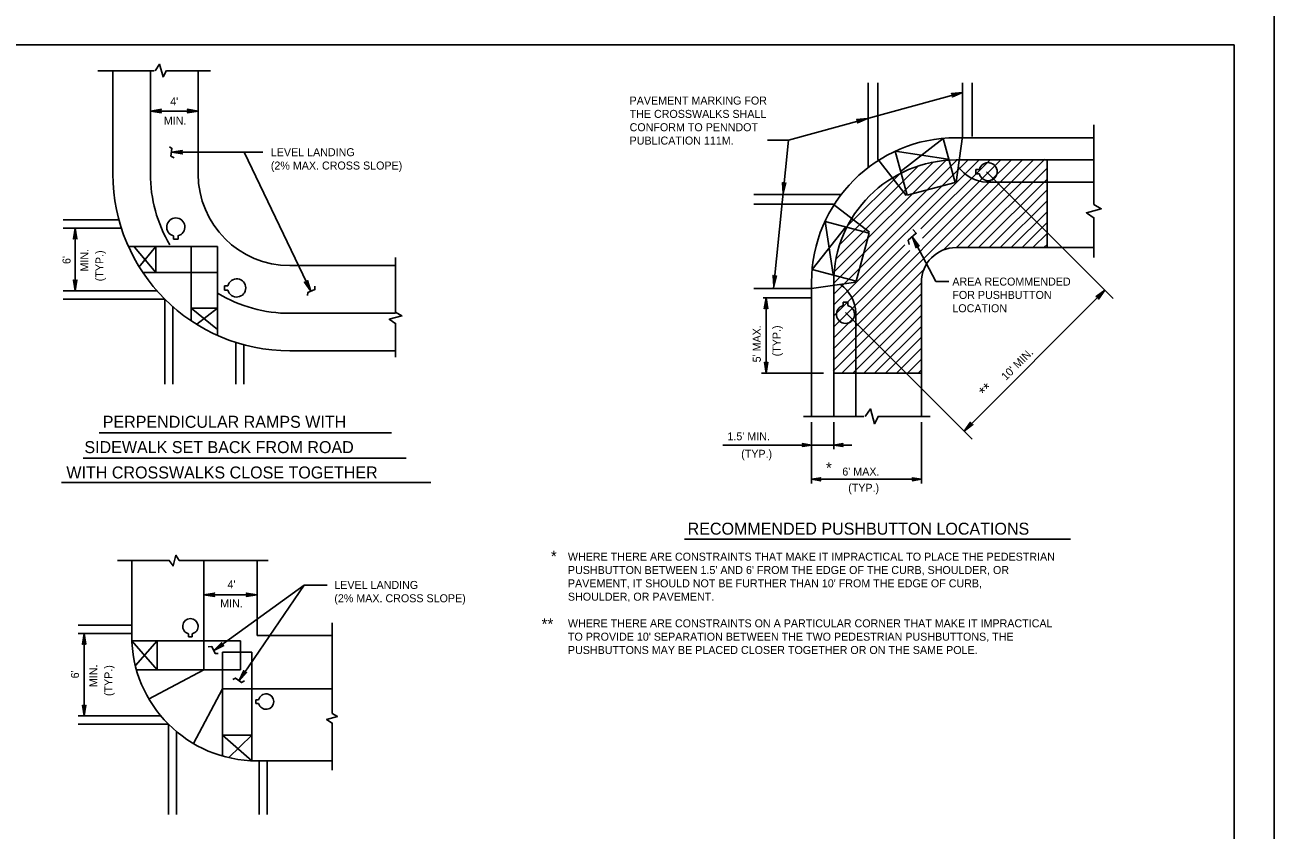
# Model space of a CAD drawing. Extents: x 36 to 940, y -1166 to 1210.
# Drawn here: x 408.6 to 876.9, y -881.2 to -579.3 of the extents above; entities that cross this region are included whole.
import ezdxf

# ---------------------------------------------------------------- set-up
doc = ezdxf.new("R2010")
doc.units = 0
for name, color, linetype in [('1', 7, 'Continuous'), ('2', 7, 'Continuous'), ('PLT-BNDY', 7, 'Continuous')]:
    doc.layers.add(name, color=color, linetype=linetype)

msp = doc.modelspace()

# ---------------------------------------------------------------- linework, layer by layer
at = {"layer": '1'}
for p in [(75.86, -586.83), (861.86, -1150.83)]:
    msp.add_line(p, (861.86, -586.83), dxfattribs=at)
at = {"layer": '2'}
for p, q in [((457, -596.52), (435.99, -596.52)), ((441.58, -596.52), (441.58, -635.21)), ((455.74, -635.21), (455.74, -596.52)), ((478.16, -596.52), (461.63, -596.52)), ((473.55, -596.52), (473.55, -635.21)), ((724.73, -632.8), (724.73, -601)), ((728.34, -629.69), (728.34, -601)), ((760.03, -621.2), (760.03, -601)), ((763.64, -621.2), (763.64, -601)), ((694.86, -622.48), (760.03, -604.62)), ((473.55, -611.6), (455.74, -611.6)), ((809.33, -646.61), (809.33, -616.73)), ((694.86, -622.48), (687.02, -622.48)), ((694.86, -622.48), (689.22, -678.1)), ((752.88, -621.85), (736.76, -634.41)), ((757.31, -638.38), (752.88, -621.85)), ((757.68, -638.28), (760.03, -621.2)), ((809.33, -621.63), (757.68, -621.63)), ((463.58, -627.06), (497.74, -627.06)), ((490.74, -627.06), (515.74, -679.16)), ((739.29, -643.21), (734.86, -626.67)), ((734.86, -626.67), (754.56, -629.71)), ((711.63, -700.88), (782.74, -629.77)), ((711.66, -696.76), (778.63, -629.8)), ((711.76, -684.4), (766.27, -629.89)), ((711.79, -680.29), (762.15, -629.92)), ((711.82, -676.17), (758.03, -629.96)), ((712.03, -671.87), (753.78, -630.12)), ((712.6, -667.21), (749.03, -630.78)), ((714.05, -661.68), (743.67, -632.05)), ((738.92, -643.31), (728.34, -629.69)), ((744.42, -655.83), (770.39, -629.86)), ((745.03, -659.3), (774.51, -629.83)), ((752.85, -663.74), (786.86, -629.73)), ((809.33, -629.96), (757.68, -629.96)), ((757.87, -662.81), (790.98, -629.7)), ((791.76, -662.81), (791.76, -629.7)), ((716.59, -655.05), (736.66, -634.97)), ((761.96, -662.81), (791.76, -633.01)), ((765.12, -633.52), (765.12, -635.17)), ((766.42, -633.52), (765.12, -633.52)), ((765.12, -635.17), (766.42, -635.17)), ((816.56, -681.88), (769.02, -634.35)), ((739.29, -643.21), (757.31, -638.38)), ((766.05, -662.81), (791.76, -637.1)), ((809.33, -638.28), (769.2, -638.28)), ((770.13, -662.81), (791.76, -641.18)), ((714.67, -642.87), (681.91, -642.87)), ((774.22, -662.81), (791.76, -645.27)), ((711.55, -646.48), (681.91, -646.48)), ((725.18, -657.05), (711.55, -646.48)), ((778.31, -662.81), (791.76, -649.36)), ((443.85, -652.43), (422.94, -652.43)), ((444.76, -655.5), (422.94, -655.5)), ((427.45, -679.04), (427.45, -655.5)), ((703.71, -671.01), (716.3, -655.08)), ((725.08, -657.43), (708.54, -652.99)), ((708.54, -652.99), (711.6, -672.88)), ((782.4, -662.81), (791.76, -653.44)), ((809.33, -666.51), (809.33, -651.6)), ((464.33, -658.41), (464.33, -659.71)), ((464.33, -659.71), (465.99, -659.71)), ((465.99, -659.71), (465.99, -658.41)), ((720.25, -675.45), (725.08, -657.43)), ((741.37, -658.97), (750.03, -675.48)), ((786.48, -662.81), (791.76, -657.53)), ((480.74, -662.38), (447.4, -662.38)), ((457.63, -672.17), (449.7, -662.65)), ((457.63, -662.38), (451.34, -670.22)), ((457.63, -662.38), (457.63, -672.17)), ((470.95, -662.38), (470.95, -690.29)), ((480.74, -662.38), (480.74, -695.72)), ((711.69, -692.64), (740.38, -663.96)), ((711.73, -688.52), (738.44, -661.81)), ((809.33, -662.81), (757.68, -662.81)), ((790.57, -662.81), (791.76, -661.62)), ((547.58, -687), (547.58, -666.58)), ((480.74, -672.17), (452.83, -672.17)), ((547.58, -669.57), (507.91, -669.57)), ((720.25, -675.45), (703.71, -671.01)), ((711.6, -705), (745.49, -671.1)), ((483.41, -678.78), (483.41, -677.13)), ((483.41, -677.13), (484.71, -677.13)), ((484.71, -678.78), (483.41, -678.78)), ((703.5, -678.1), (681.91, -678.1)), ((720.15, -675.82), (703.5, -678.1)), ((703.5, -726.17), (703.5, -675.82)), ((711.57, -709.12), (744.68, -676.01)), ((711.82, -726.17), (711.82, -675.82)), ((744.68, -726.17), (744.68, -675.82)), ((755.01, -675.48), (750.03, -675.48)), ((760.67, -731.62), (813.49, -678.81)), ((458.12, -679.04), (422.94, -679.04)), ((461.01, -682.11), (422.94, -682.11)), ((461.01, -682.11), (461.01, -714.01)), ((703.5, -681.72), (685.41, -681.72)), ((686.44, -709.9), (686.44, -681.72)), ((714.87, -709.9), (744.68, -680.1)), ((715.38, -683.26), (717.04, -683.26)), ((715.38, -684.56), (715.38, -683.26)), ((717.04, -683.26), (717.04, -684.56)), ((464.08, -684.99), (464.08, -714.01)), ((480.74, -685.48), (470.95, -685.48)), ((470.95, -685.48), (480.8, -693.54)), ((480.74, -685.48), (473.03, -691.5)), ((547.58, -687.47), (507.91, -687.47)), ((763.75, -734.69), (716.21, -687.16)), ((718.96, -709.9), (744.68, -684.18)), ((720.15, -726.17), (720.15, -687.33)), ((723.05, -709.9), (744.68, -688.27)), ((547.58, -703.91), (547.58, -691.24)), ((727.14, -709.9), (744.68, -692.36)), ((731.22, -709.9), (744.68, -696.44)), ((487.61, -698.36), (487.61, -714.01)), ((490.68, -699.26), (490.68, -714.01)), ((547.58, -701.54), (507.91, -701.54)), ((735.31, -709.9), (744.68, -700.53)), ((739.4, -709.9), (744.68, -704.62)), ((708.02, -709.9), (684.68, -709.9)), ((744.68, -709.9), (711.56, -709.9)), ((743.48, -709.9), (744.68, -708.71)), ((723.06, -726.17), (700.5, -726.17)), ((703.5, -751.29), (703.5, -728.34)), ((711.82, -738.46), (711.82, -728.34)), ((747.95, -726.17), (728.5, -726.17)), ((744.68, -751.29), (744.68, -728.34)), ((545.97, -732.32), (436.4, -732.32)), ((703.5, -736.86), (670.18, -736.86)), ((711.82, -736.86), (703.5, -736.86)), ((718.58, -736.86), (711.82, -736.86)), ((551.49, -741.73), (430.47, -741.73)), ((560.81, -750.94), (422.33, -750.94)), ((744.68, -749.7), (703.5, -749.7)), ((800.5, -772.21), (655.84, -772.21)), ((443.3, -780.18), (462.83, -780.18)), ((448.63, -780.18), (448.63, -808.32)), ((466.44, -780.18), (499.73, -780.18)), ((475.63, -780.18), (475.63, -821.23)), ((495.63, -780.18), (495.63, -808.31)), ((513.27, -789.38), (479.44, -813.91)), ((513.27, -789.38), (488.9, -825.19)), ((521.87, -789.38), (513.27, -789.38)), ((495.63, -793.01), (475.63, -793.01)), ((448.63, -804.47), (428.55, -804.47)), ((523.75, -837.5), (523.75, -803.53)), ((448.63, -807.54), (428.55, -807.54)), ((430.79, -838.47), (430.79, -807.54)), ((469.92, -807.65), (469.92, -808.75)), ((469.92, -808.75), (471.33, -808.75)), ((471.33, -808.75), (471.33, -807.65)), ((523.75, -808.31), (495.63, -808.31)), ((489.36, -810.31), (448.63, -810.31)), ((458.24, -821.23), (448.63, -810.31)), ((458.24, -810.31), (450.11, -819.58)), ((458.24, -810.31), (458.24, -821.23)), ((482.71, -814.58), (482.71, -853.5)), ((493.63, -814.58), (482.71, -814.58)), ((489.36, -810.31), (489.36, -821.23)), ((493.63, -814.58), (493.63, -855.3)), ((489.36, -821.23), (450.44, -821.23)), ((475.63, -821.23), (454.89, -832.21)), ((482.71, -828.31), (471.84, -848.84)), ((523.75, -828.31), (482.71, -828.31)), ((495.11, -833.78), (495.11, -832.37)), ((495.11, -832.37), (496.22, -832.37)), ((496.22, -833.78), (495.11, -833.78)), ((459.58, -838.47), (428.55, -838.47)), ((462.39, -841.54), (428.55, -841.54)), ((462.39, -841.54), (462.39, -875.38)), ((523.75, -858.74), (523.75, -841.1)), ((465.46, -844.35), (465.46, -875.38)), ((493.63, -845.69), (482.71, -845.69)), ((482.71, -845.69), (493.63, -855.3)), ((493.63, -845.69), (484.89, -854.16)), ((523.75, -855.3), (495.61, -855.3)), ((496.4, -855.3), (496.4, -875.38)), ((499.47, -855.3), (499.47, -875.38))]:
    msp.add_line(p, q, dxfattribs=at)
for points in [[(457.43, -596.54), (459.11, -594.06), (460.38, -598.8), (461.74, -596.43)], [(756.18, -605.17), (756.39, -605.4), (760.03, -604.62), (756.18, -605.17), (755.94, -605.06), (760.03, -604.62), (756.5, -605.78), (756.44, -606.08), (760.03, -604.62), (756.29, -606.31), (756.44, -606.08)], [(459.6, -612.09), (459.46, -611.81), (455.74, -611.6), (459.6, -612.09), (459.8, -612.26), (455.74, -611.6), (459.46, -611.42), (459.59, -611.14), (455.74, -611.6), (459.8, -610.96), (459.59, -611.14)], [(469.69, -611.12), (469.83, -611.4), (473.55, -611.6), (469.69, -611.12), (469.49, -610.95), (473.55, -611.6), (469.83, -611.79), (469.7, -612.06), (473.55, -611.6), (469.49, -612.25), (469.7, -612.06)], [(720.64, -614.91), (720.85, -615.15), (724.49, -614.36), (720.64, -614.91), (720.4, -614.8), (724.49, -614.36), (720.96, -615.52), (720.9, -615.82), (724.49, -614.36), (720.74, -616.06), (720.9, -615.82)], [(464.57, -629.16), (463.35, -628.47), (463.71, -625.62), (462.77, -624.98)], [(467.44, -627.54), (467.3, -627.26), (463.58, -627.06), (467.44, -627.54), (467.64, -627.71), (463.58, -627.06), (467.29, -626.88), (467.43, -626.6), (463.58, -627.06), (467.64, -626.42), (467.43, -626.6)], [(693.7, -638.74), (693.4, -638.86), (692.82, -642.53), (693.7, -638.74), (693.88, -638.56), (692.82, -642.53), (693.02, -638.82), (692.76, -638.66), (692.82, -642.53), (692.59, -638.43), (692.76, -638.66)], [(809.43, -651.75), (806.51, -649.76), (812.08, -648.28), (809.3, -646.68)], [(426.97, -659.36), (427.24, -659.22), (427.45, -655.5), (426.97, -659.36), (426.8, -659.56), (427.45, -655.5), (427.63, -659.21), (427.91, -659.35), (427.45, -655.5), (428.09, -659.56), (427.91, -659.35)], [(741.43, -656.03), (742.72, -657.47), (739.67, -660.09), (740.05, -661.63)], [(742.73, -662.61), (742.91, -662.35), (741.37, -658.97), (742.73, -662.61), (742.67, -662.86), (741.37, -658.97), (743.25, -662.17), (743.56, -662.16), (741.37, -658.97), (743.82, -662.26), (743.56, -662.16)], [(690.17, -673.59), (689.87, -673.7), (689.3, -677.38), (690.17, -673.59), (690.35, -673.41), (689.3, -677.38), (689.49, -673.67), (689.23, -673.5), (689.3, -677.38), (689.06, -673.28), (689.23, -673.5)], [(427.93, -675.18), (427.65, -675.32), (427.45, -679.04), (427.93, -675.18), (428.1, -674.98), (427.45, -679.04), (427.27, -675.33), (426.99, -675.19), (427.45, -679.04), (426.81, -674.98), (426.99, -675.19)], [(514.51, -675.47), (514.32, -675.72), (515.74, -679.16), (514.51, -675.47), (514.57, -675.22), (515.74, -679.16), (513.97, -675.89), (513.66, -675.89), (515.74, -679.16), (513.4, -675.78), (513.66, -675.89)], [(517.24, -677.23), (517.29, -678.58), (514.64, -679.68), (514.55, -680.82)], [(810.41, -681.2), (810.71, -681.29), (813.49, -678.81), (810.41, -681.2), (810.15, -681.22), (813.49, -678.81), (810.99, -681.57), (811.09, -681.86), (813.49, -678.81), (811.07, -682.13), (811.09, -681.86)], [(685.95, -685.58), (686.23, -685.43), (686.44, -681.72), (685.95, -685.58), (685.78, -685.78), (686.44, -681.72), (686.62, -685.43), (686.9, -685.57), (686.44, -681.72), (687.08, -685.78), (686.9, -685.57)], [(547.66, -691.36), (545.18, -689.68), (549.91, -688.41), (547.55, -687.05)], [(686.92, -706.04), (686.64, -706.18), (686.44, -709.9), (686.92, -706.04), (687.09, -705.84), (686.44, -709.9), (686.25, -706.18), (685.98, -706.05), (686.44, -709.9), (685.79, -705.84), (685.98, -706.05)], [(723.56, -726.2), (725.54, -723.29), (727.03, -728.86), (728.63, -726.08)], [(763.75, -729.23), (763.45, -729.14), (760.67, -731.62), (763.75, -729.23), (764.01, -729.21), (760.67, -731.62), (763.17, -728.87), (763.07, -728.57), (760.67, -731.62), (763.09, -728.3), (763.07, -728.57)], [(700.22, -736.45), (700.34, -736.69), (703.5, -736.86), (700.22, -736.45), (700.05, -736.31), (703.5, -736.86), (700.34, -737.02), (700.23, -737.25), (703.5, -736.86), (700.05, -737.41), (700.23, -737.25)], [(715.1, -737.27), (714.98, -737.04), (711.82, -736.86), (715.1, -737.27), (715.27, -737.42), (711.82, -736.86), (714.98, -736.71), (715.09, -736.47), (711.82, -736.86), (715.27, -736.31), (715.09, -736.47)], [(706.78, -750.11), (706.66, -749.87), (703.5, -749.7), (706.78, -750.11), (706.95, -750.25), (703.5, -749.7), (706.65, -749.54), (706.77, -749.3), (703.5, -749.7), (706.95, -749.15), (706.77, -749.3)], [(741.39, -749.28), (741.52, -749.52), (744.68, -749.7), (741.39, -749.28), (741.23, -749.14), (744.68, -749.7), (741.52, -749.85), (741.4, -750.09), (744.68, -749.7), (741.23, -750.24), (741.4, -750.09)], [(462.72, -780.11), (464.16, -782.22), (465.23, -778.19), (466.39, -780.21)], [(479.49, -793.5), (479.34, -793.22), (475.63, -793.01), (479.49, -793.5), (479.69, -793.66), (475.63, -793.01), (479.34, -792.83), (479.48, -792.55), (475.63, -793.01), (479.69, -792.37), (479.48, -792.55)], [(491.77, -792.53), (491.91, -792.81), (495.63, -793.01), (491.77, -792.53), (491.57, -792.36), (495.63, -793.01), (491.91, -793.19), (491.78, -793.47), (495.63, -793.01), (491.57, -793.66), (491.78, -793.47)], [(430.31, -811.4), (430.58, -811.25), (430.79, -807.54), (430.31, -811.4), (430.14, -811.59), (430.79, -807.54), (430.97, -811.25), (431.25, -811.39), (430.79, -807.54), (431.43, -811.59), (431.25, -811.39)], [(477.35, -812.53), (478.7, -812.42), (479.92, -815.01), (481.06, -815.05)], [(482.85, -812.03), (482.57, -811.89), (479.44, -813.91), (482.85, -812.03), (483.11, -812.05), (479.44, -813.91), (482.34, -811.58), (482.29, -811.27), (479.44, -813.91), (482.35, -811), (482.29, -811.27)], [(491.47, -822.27), (491.16, -822.23), (488.9, -825.19), (491.47, -822.27), (491.72, -822.2), (488.9, -825.19), (490.83, -822.02), (490.68, -821.75), (488.9, -825.19), (490.65, -821.47), (490.68, -821.75)], [(490.97, -825.26), (489.82, -825.98), (487.54, -824.25), (486.52, -824.74)], [(431.27, -834.61), (430.99, -834.76), (430.79, -838.47), (431.27, -834.61), (431.44, -834.42), (430.79, -838.47), (430.61, -834.76), (430.33, -834.63), (430.79, -838.47), (430.15, -834.42), (430.33, -834.63)], [(523.82, -841.21), (521.71, -839.78), (525.74, -838.7), (523.73, -837.55)]]:
    msp.add_lwpolyline(points, dxfattribs=at)
for centre, radius, start, end in [((757.68, -675.82), 54.19, 90, 180), ((757.68, -675.82), 45.86, 90, 180), ((769.71, -634.35), 3.4, 194.1014, 165.8986), ((507.91, -635.21), 66.33, 180, 270), ((507.91, -635.21), 52.26, 180, 210.6115), ((507.91, -635.21), 34.36, 180, 270), ((769.79, -624.38), 13.9, 215.5875, 267.5634), ((465.16, -655.12), 3.4, 284.1014, 255.8986), ((757.68, -675.82), 13.01, 90, 180), ((488, -677.96), 3.4, 194.1014, 165.8986), ((706.24, -687.92), 13.9, 2.4366, 54.4125), ((507.91, -635.21), 52.26, 239.0766, 270), ((716.21, -687.85), 3.4, 104.1014, 75.8986), ((470.63, -804.85), 2.89, 284.1014, 255.8986), ((495.61, -808.32), 46.98, 180, 270), ((499.02, -833.07), 2.89, 194.1014, 165.8986)]:
    msp.add_arc(centre, radius, start, end, dxfattribs=at)
at = {"layer": 'PLT-BNDY'}
msp.add_lwpolyline([(35.86, -571.83), (876.86, -571.83), (876.86, -1165.83), (35.86, -1165.83)], close=True, dxfattribs=at)

# ---------------------------------------------------------------- texts
at = {"layer": '2'}
for s, height, p in [("4'", 3, (463.07, -609.5)), ('PAVEMENT MARKING FOR', 3.0001, (635.28, -609.18)), ('THE CROSSWALKS SHALL', 3.0001, (635.28, -614.18)), ('MIN.', 3, (460.68, -616.69)), ('CONFORM TO PENNDOT', 3.0001, (635.28, -619.18)), ('PUBLICATION 111M.', 3.0001, (635.28, -624.18)), ('LEVEL LANDING', 3, (500.79, -628.55)), ('(2% MAX. CROSS SLOPE)', 3, (500.79, -633.55)), ('AREA RECOMMENDED', 3.0001, (756.27, -677.07)), ('FOR PUSHBUTTON', 3.0001, (756.27, -682.07)), ('LOCATION', 3, (756.27, -687.07)), ('PERPENDICULAR RAMPS WITH', 4.5, (437.78, -730.4)), ("1.5' MIN.", 3, (671.96, -735.09)), ('SIDEWALK SET BACK FROM ROAD', 4.5, (430.9, -739.9)), ('(TYP.)', 3, (677.11, -741.66)), ('*', 4.2, (708.9, -747.54)), ('WITH CROSSWALKS CLOSE TOGETHER', 4.5, (424.15, -749.4)), ("6' MAX.", 3, (715.02, -748.32)), ('(TYP.)', 3, (717.23, -754.41)), ('RECOMMENDED PUSHBUTTON LOCATIONS', 4.5, (657.04, -770.48)), ('*', 4.2, (605.78, -780.69)), ('WHERE THERE ARE CONSTRAINTS THAT MAKE IT IMPRACTICAL TO PLACE THE PEDESTRIAN', 3, (612.16, -780.23)), ("PUSHBUTTON BETWEEN 1.5' AND 6' FROM THE EDGE OF THE CURB, SHOULDER, OR", 3, (612.16, -785.23)), ("4'", 3, (484.53, -790.64)), ('LEVEL LANDING', 3, (524.59, -790.83)), ("PAVEMENT, IT SHOULD NOT BE FURTHER THAN 10' FROM THE EDGE OF CURB, ", 3, (612.16, -790.23)), ('MIN.', 3, (481.82, -797.78)), ('(2% MAX. CROSS SLOPE)', 3, (524.59, -795.83)), ('SHOULDER, OR PAVEMENT.', 3, (612.16, -795.23)), ('**', 4.2, (602.3, -806.06)), ('WHERE THERE ARE CONSTRAINTS ON A PARTICULAR CORNER THAT MAKE IT IMPRACTICAL', 3, (612.16, -805.23)), ("TO PROVIDE 10' SEPARATION BETWEEN THE TWO PEDESTRIAN PUSHBUTTONS, THE ", 3, (612.16, -810.23)), ('PUSHBUTTONS MAY BE PLACED CLOSER TOGETHER OR ON THE SAME POLE.', 3, (612.16, -815.23))]:
    msp.add_text(s, height=height, dxfattribs=at).set_placement(p)
for s, height, rotation, p in [('MIN.', 3, 90, (432.42, -671.79)), ('(TYP.)', 3, 90, (438.06, -675.45)), ("6'", 3, 90, (425.71, -668.98)), ("5' MAX.", 3, 90, (684.47, -705.85)), ('(TYP.)', 3, 90, (691.88, -703.6)), ("10' MIN.", 3, 45, (776.36, -712.87)), ('**', 4.2, 45, (768.78, -719.22)), ("6'", 3, 90, (428.86, -824.37)), ('MIN.', 3, 90, (435.76, -827.64)), ('(TYP.)', 3, 90, (441.4, -831))]:
    msp.add_text(s, height=height, rotation=rotation, dxfattribs=at).set_placement(p)

doc.saveas('drawing.dxf')
